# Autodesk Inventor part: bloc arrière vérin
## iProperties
Shininess: 20.0
Angle Display Precision: 2
Document Length Units: 11269
Document Angle Units: 11279
Document Time Units: 11290
Document Mass Units: 11283
Document Length Units Precision: 3
Document Angle Units Precision: 2
Created: 2002-09
Part Number: bloc arrière vérin
Material: Par défaut
Document SubType Name: Modélisation
Designer: administrateur
Density: 0.0
Volumn: 0.0
Area: 0.0
PropertySet Name: Model Information
Control State: 0
Master: False
Checked Out: False
Author: administrateur
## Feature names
1. Base1
